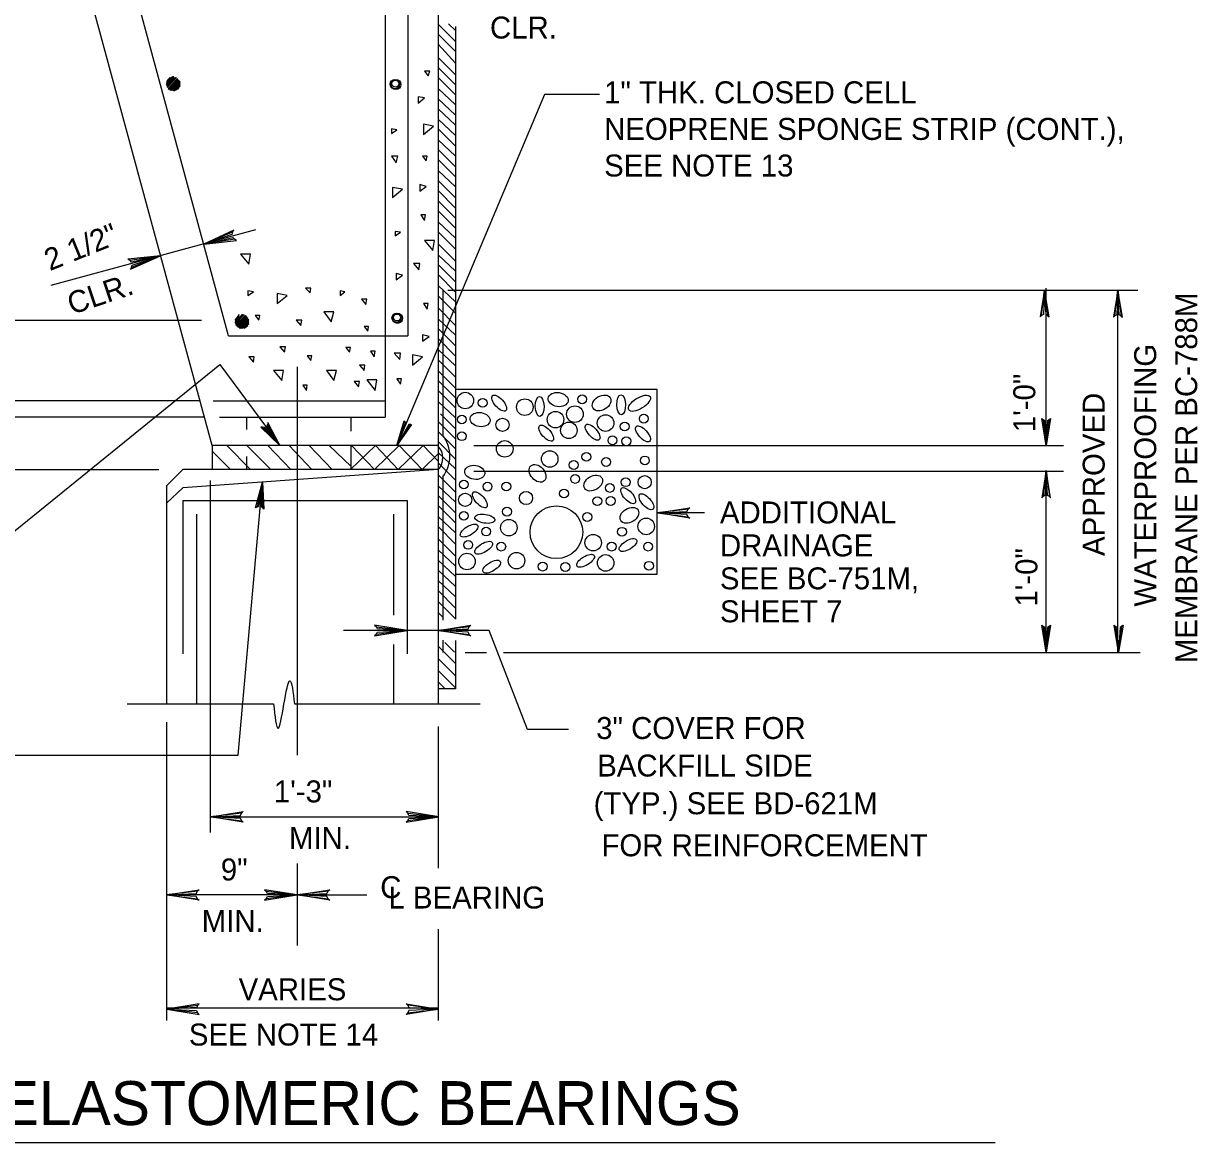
# Model space of a CAD drawing. Extents: x 640009 to 641706, y 298547 to 299735.
# Drawn here: x 640480.1 to 640640.5, y 298864.4 to 299017.2 of the extents above; entities that cross this region are included whole.
import ezdxf

# ---------------------------------------------------------------- set-up
doc = ezdxf.new("R2010")
doc.units = 0
doc.layers.add('1', color=7, linetype='Continuous')

msp = doc.modelspace()

# ---------------------------------------------------------------- linework, layer by layer
at = {"layer": '1'}
for p, q in [((640536.74, 299073.94), (640536.74, 298959.5)), ((640532.61, 299068.69), (640532.61, 299014.94)), ((640508.11, 298974.56), (640484.77, 299060.46)), ((640505.86, 298959.56), (640480.36, 299053.44)), ((640529.49, 299051.81), (640529.49, 298963.44)), ((640539.11, 299016.79), (640539.11, 298935.88)), ((640532.61, 299014.94), (640532.61, 298981.69)), ((640551.28, 299007.52), (640531.11, 298959.56)), ((640558.79, 299007.52), (640551.28, 299007.52)), ((640511.77, 298989), (640483.82, 298981.41)), ((640532.61, 298982.31), (640532.61, 298974.56)), ((640537.36, 298980.79), (640537.36, 298960.94)), ((640538.04, 298980.79), (640632.32, 298980.79)), ((640619.78, 298959.56), (640619.78, 298981.04)), ((640629.58, 298931.31), (640629.58, 298980.79)), ((640453.19, 298976.69), (640504.41, 298976.69)), ((640508.11, 298974.56), (640532.61, 298974.56)), ((640464.53, 298936.31), (640506.9, 298970.62)), ((640506.9, 298970.62), (640515.11, 298959.56)), ((640517.49, 298970.31), (640517.49, 298917.29)), ((640504.11, 298965.69), (640465.39, 298965.69)), ((640505.99, 298965.69), (640529.49, 298965.69)), ((640504.74, 298963.44), (640413.24, 298963.44)), ((640506.86, 298963.44), (640529.49, 298963.44)), ((640510.61, 298961.75), (640510.61, 298963.44)), ((640524.86, 298961.54), (640524.86, 298963.44)), ((640505.86, 298959.56), (640505.86, 298956.31)), ((640505.86, 298959.56), (640505.86, 298956.31)), ((640524.86, 298959.56), (640505.86, 298959.56)), ((640524.78, 298956.31), (640528.16, 298959.56)), ((640524.86, 298956.31), (640524.86, 298959.56)), ((640536.74, 298959.56), (640524.86, 298959.56)), ((640528.03, 298956.31), (640531.41, 298959.56)), ((640531.29, 298956.31), (640534.67, 298959.56)), ((640536.74, 298959.56), (640536.74, 298956.31)), ((640541.6, 298959.56), (640622.15, 298959.56)), ((640510.61, 298956.31), (640510.61, 298958.06)), ((640534.54, 298956.31), (640536.74, 298958.43)), ((640460.32, 298956.31), (640498.58, 298956.31)), ((640499.61, 298954.06), (640501.86, 298956.31)), ((640536.74, 298956.31), (640501.86, 298953.81)), ((640505.86, 298956.31), (640501.86, 298956.31)), ((640524.86, 298956.31), (640505.86, 298956.31)), ((640536.74, 298956.31), (640524.86, 298956.31)), ((640536.74, 298956.31), (640536.74, 298924.31)), ((640541.6, 298956.06), (640622.15, 298956.06)), ((640619.78, 298931.31), (640619.78, 298956.06)), ((640499.61, 298954.06), (640499.61, 298924.31)), ((640505.61, 298954.81), (640505.61, 298906.71)), ((640537.36, 298955.31), (640537.36, 298935.74)), ((640499.61, 298951.69), (640501.86, 298953.81)), ((640509.4, 298917.29), (640512.65, 298953.55)), ((640501.86, 298952.06), (640532.52, 298952.06)), ((640501.86, 298952.06), (640501.86, 298931.13)), ((640505.61, 298951.81), (640505.61, 298951.81)), ((640532.52, 298952.06), (640532.52, 298931.13)), ((640503.74, 298950.18), (640503.74, 298924.31)), ((640530.64, 298950.18), (640530.64, 298936.41)), ((640573.13, 298950.36), (640566.65, 298950.36)), ((640536.74, 298934.32), (640523.81, 298934.32)), ((640543.68, 298934.32), (640536.74, 298934.32)), ((640548.95, 298920.8), (640543.68, 298934.32)), ((640530.64, 298932.39), (640530.64, 298924.31)), ((640537.36, 298933.01), (640537.36, 298931.31)), ((640539.11, 298932.94), (640539.11, 298926.34)), ((640540.4, 298931.31), (640543.34, 298931.31)), ((640545.65, 298931.31), (640632.61, 298931.31)), ((640539.11, 298926.34), (640536.74, 298926.34)), ((640494.24, 298924.31), (640514.24, 298924.31)), ((640517.11, 298924.31), (640542.49, 298924.31)), ((640499.61, 298921.81), (640499.61, 298881.07)), ((640536.74, 298921.19), (640536.74, 298901.88)), ((640554.54, 298920.8), (640548.95, 298920.8)), ((640433.57, 298917.29), (640509.4, 298917.29)), ((640536.74, 298908.84), (640505.61, 298908.84)), ((640517.49, 298902.5), (640517.49, 298891.31)), ((640517.49, 298898.2), (640499.61, 298898.2)), ((640517.49, 298898.2), (640527, 298898.2)), ((640536.74, 298893.53), (640536.74, 298881.07)), ((640536.74, 298882.75), (640499.61, 298882.75)), ((640431.62, 298864.4), (640612.82, 298864.4))]:
    msp.add_line(p, q, dxfattribs=at)
for points in [[(640539.11, 299014.73), (640536.74, 299017.1)], [(640539.11, 299016.25), (640538.15, 299017.15)], [(640539.11, 299013.35), (640536.74, 299015.73)], [(640539.11, 299011.78), (640536.74, 299014.35)], [(640539.11, 299010.2), (640536.74, 299012.57)], [(640539.11, 299008.82), (640536.74, 299011.2)], [(640499.61, 299008.94), (640500.49, 299009.94)], [(640499.61, 299008.81), (640500.61, 299009.94)], [(640499.61, 299008.94), (640500.61, 299009.94)], [(640499.61, 299009.06), (640500.49, 299009.94)], [(640499.61, 299008.69), (640500.74, 299009.81)], [(640499.61, 299009.19), (640500.24, 299009.81)], [(640499.74, 299008.44), (640500.99, 299009.81)], [(640499.74, 299008.56), (640500.99, 299009.81)], [(640499.74, 299008.56), (640500.86, 299009.81)], [(640499.74, 299009.31), (640500.11, 299009.81)], [(640499.86, 299008.31), (640501.11, 299009.69)], [(640499.86, 299008.31), (640501.11, 299009.69)], [(640499.86, 299008.19), (640501.24, 299009.56)], [(640499.99, 299008.19), (640501.24, 299009.56)], [(640499.99, 299008.19), (640501.36, 299009.44)], [(640500.11, 299008.06), (640501.36, 299009.44)], [(640500.24, 299008.06), (640501.36, 299009.31)], [(640500.24, 299008.06), (640501.49, 299009.31)], [(640500.24, 299008.06), (640501.36, 299009.31)], [(640500.36, 299008.06), (640501.49, 299009.19)], [(640500.49, 299008.06), (640501.49, 299009.06)], [(640500.61, 299007.94), (640501.49, 299008.94)], [(640500.74, 299008.06), (640501.49, 299008.81)], [(640500.86, 299008.06), (640501.49, 299008.69)], [(640539.11, 299007.45), (640536.74, 299009.82)], [(640501.11, 299008.19), (640501.36, 299008.44)], [(640539.11, 299006.1), (640536.74, 299008.32)], [(640539.11, 299004.7), (640536.74, 299006.92)], [(640539.11, 299003.3), (640536.74, 299005.52)], [(640539.11, 299001.9), (640536.74, 299004.12)], [(640539.11, 299000.45), (640536.74, 299002.82)], [(640539.11, 298999.1), (640536.74, 299001.32)], [(640539.11, 298997.62), (640536.74, 299000)], [(640539.11, 298996.25), (640536.74, 298998.63)], [(640539.11, 298994.9), (640536.74, 298997.13)], [(640539.11, 298993.37), (640536.74, 298995.75)], [(640539.11, 298992), (640536.74, 298994.38)], [(640539.11, 298990.62), (640536.74, 298993)], [(640539.11, 298989.25), (640536.74, 298991.63)], [(640539.11, 298987.9), (640536.74, 298990.13)], [(640508.66, 298988.73), (640508.57, 298988.38), (640504.71, 298987.08), (640508.66, 298988.73), (640508.81, 298988.97), (640504.71, 298987.08), (640508.68, 298987.98), (640508.92, 298987.73), (640504.71, 298987.08), (640509.2, 298987.57), (640508.92, 298987.73)], [(640539.11, 298986.37), (640536.74, 298988.75)], [(640539.11, 298984.72), (640536.74, 298987.09)], [(640494.86, 298983.86), (640494.95, 298984.21), (640498.82, 298985.48), (640494.86, 298983.86), (640494.71, 298983.63), (640498.82, 298985.48), (640494.84, 298984.62), (640494.61, 298984.87), (640498.82, 298985.48), (640494.33, 298985.03), (640494.61, 298984.87)], [(640539.11, 298983.37), (640536.74, 298985.59)], [(640539.11, 298981.9), (640536.74, 298984.27)], [(640539.11, 298980.52), (640536.74, 298982.9)], [(640539.11, 298979.17), (640536.74, 298981.4)], [(640539.11, 298977.65), (640536.74, 298980.02)], [(640620.02, 298977.3), (640619.76, 298977.45), (640619.57, 298980.84), (640620.02, 298977.3), (640620.18, 298977.13), (640619.57, 298980.84), (640619.41, 298977.45), (640619.16, 298977.32), (640619.57, 298980.84), (640618.97, 298977.13), (640619.16, 298977.32)], [(640630.03, 298977.25), (640629.77, 298977.4), (640629.58, 298980.79), (640630.03, 298977.25), (640630.19, 298977.08), (640629.58, 298980.79), (640629.42, 298977.4), (640629.16, 298977.27), (640629.58, 298980.79), (640628.98, 298977.08), (640629.16, 298977.27)], [(640539.11, 298975.98), (640536.74, 298978.36)], [(640508.99, 298976.19), (640510.24, 298977.44)], [(640508.99, 298976.31), (640510.11, 298977.44)], [(640508.99, 298976.31), (640509.99, 298977.44)], [(640508.99, 298976.44), (640509.99, 298977.44)], [(640508.99, 298976.69), (640509.61, 298977.44)], [(640508.99, 298976.56), (640509.61, 298977.19)], [(640509.11, 298975.94), (640510.49, 298977.31)], [(640509.11, 298976.06), (640510.36, 298977.31)], [(640509.11, 298976.06), (640510.36, 298977.31)], [(640509.24, 298975.81), (640510.61, 298977.19)], [(640509.24, 298975.94), (640510.49, 298977.19)], [(640509.36, 298975.69), (640510.74, 298977.06)], [(640509.36, 298975.81), (640510.61, 298977.06)], [(640509.49, 298975.69), (640510.74, 298976.94)], [(640509.49, 298975.69), (640510.74, 298976.94)], [(640509.49, 298975.69), (640510.74, 298976.81)], [(640509.61, 298975.56), (640510.86, 298976.81)], [(640509.74, 298975.56), (640510.86, 298976.69)], [(640509.86, 298975.56), (640510.86, 298976.56)], [(640509.86, 298975.56), (640510.86, 298976.44)], [(640539.11, 298974.63), (640536.74, 298976.86)], [(640509.99, 298975.56), (640510.86, 298976.31)], [(640510.24, 298975.56), (640510.86, 298976.19)], [(640510.36, 298975.69), (640510.74, 298975.94)], [(640539.11, 298973.16), (640536.74, 298975.53)], [(640539.11, 298971.78), (640536.74, 298974.16)], [(640539.11, 298970.43), (640536.74, 298972.66)], [(640539.11, 298968.91), (640536.74, 298971.28)], [(640539.11, 298967.42), (640536.74, 298969.79)], [(640539.11, 298966.1), (640536.74, 298968.47)], [(640539.11, 298964.72), (640536.74, 298967.1)], [(640539.11, 298963.37), (640536.74, 298965.6)], [(640539.11, 298961.85), (640537.06, 298963.9)], [(640512.74, 298962.06), (640512.99, 298962.06), (640515.11, 298959.56), (640512.74, 298962.06), (640512.49, 298962.06), (640515.11, 298959.56), (640513.36, 298962.31), (640513.49, 298962.44), (640515.11, 298959.56), (640513.49, 298962.69), (640513.49, 298962.44)], [(640532.99, 298962.44), (640532.74, 298962.44), (640531.11, 298959.56), (640532.99, 298962.44), (640533.11, 298962.44), (640531.11, 298959.56), (640532.36, 298962.56), (640532.24, 298962.69), (640531.11, 298959.56), (640532.11, 298962.94), (640532.24, 298962.69)], [(640539.11, 298960.47), (640536.74, 298962.85)], [(640620.23, 298963.1), (640619.97, 298962.95), (640619.78, 298959.56), (640620.23, 298963.1), (640620.39, 298963.28), (640619.78, 298959.56), (640619.62, 298962.95), (640619.37, 298963.09), (640619.78, 298959.56), (640619.18, 298963.28), (640619.37, 298963.09)], [(640539.11, 298959.1), (640536.74, 298961.47)], [(640508.36, 298956.31), (640505.86, 298958.81)], [(640511.11, 298956.31), (640507.86, 298959.56)], [(640513.86, 298956.31), (640510.61, 298959.56)], [(640516.61, 298956.31), (640513.49, 298959.56)], [(640519.49, 298956.31), (640516.36, 298959.56)], [(640522.24, 298956.31), (640519.11, 298959.56)], [(640524.86, 298956.69), (640521.86, 298959.56)], [(640528.03, 298956.31), (640524.91, 298959.56)], [(640531.29, 298956.31), (640528.16, 298959.56)], [(640534.54, 298956.31), (640531.41, 298959.56)], [(640536.74, 298957.41), (640534.67, 298959.56)], [(640539.11, 298957.72), (640536.74, 298960.1)], [(640539.11, 298956.37), (640536.74, 298958.6)], [(640539.11, 298954.85), (640536.74, 298957.22)], [(640539.11, 298953.19), (640536.74, 298955.57)], [(640620.22, 298952.61), (640619.96, 298952.76), (640619.77, 298956.15), (640620.22, 298952.61), (640620.37, 298952.44), (640619.77, 298956.15), (640619.61, 298952.76), (640619.35, 298952.63), (640619.77, 298956.15), (640619.17, 298952.44), (640619.35, 298952.63)], [(640512.01, 298951.19), (640512.22, 298951.32), (640512.74, 298954.56), (640512.01, 298951.19), (640511.8, 298951.06), (640512.74, 298954.56), (640512.57, 298951.24), (640512.8, 298951.09), (640512.74, 298954.56), (640512.93, 298950.88), (640512.8, 298951.09)], [(640539.11, 298951.84), (640536.74, 298954.07)], [(640539.11, 298950.37), (640536.74, 298952.74)], [(640539.11, 298948.99), (640536.74, 298951.37)], [(640570.89, 298949.82), (640570.72, 298950.14), (640566.65, 298950.36), (640570.89, 298949.82), (640571.1, 298949.63), (640566.65, 298950.36), (640570.72, 298950.56), (640570.87, 298950.86), (640566.65, 298950.36), (640571.1, 298951.08), (640570.87, 298950.86)], [(640539.11, 298947.64), (640536.74, 298949.87)], [(640539.11, 298946.12), (640536.74, 298948.49)], [(640539.11, 298944.45), (640536.74, 298946.83)], [(640539.11, 298943.1), (640536.74, 298945.33)], [(640539.11, 298941.7), (640536.74, 298943.93)], [(640539.11, 298940.3), (640536.74, 298942.53)], [(640539.08, 298938.93), (640536.74, 298941.13)], [(640539.11, 298937.38), (640536.74, 298939.75)], [(640539.11, 298935.91), (640536.74, 298938.28)], [(640537.43, 298936.08), (640536.74, 298936.78)], [(640528.28, 298933.78), (640528.45, 298934.1), (640532.52, 298934.32), (640528.28, 298933.78), (640528.06, 298933.6), (640532.52, 298934.32), (640528.45, 298934.52), (640528.29, 298934.82), (640532.52, 298934.32), (640528.06, 298935.04), (640528.29, 298934.82)], [(640540.98, 298933.78), (640540.81, 298934.1), (640536.74, 298934.32), (640540.98, 298933.78), (640541.19, 298933.6), (640536.74, 298934.32), (640540.81, 298934.52), (640540.96, 298934.82), (640536.74, 298934.32), (640541.19, 298935.04), (640540.96, 298934.82)], [(640620.22, 298934.89), (640619.96, 298934.74), (640619.77, 298931.35), (640620.22, 298934.89), (640620.37, 298935.06), (640619.77, 298931.35), (640619.61, 298934.74), (640619.35, 298934.87), (640619.77, 298931.35), (640619.17, 298935.06), (640619.35, 298934.87)], [(640630.13, 298934.89), (640629.87, 298934.74), (640629.68, 298931.35), (640630.13, 298934.89), (640630.29, 298935.06), (640629.68, 298931.35), (640629.52, 298934.74), (640629.27, 298934.87), (640629.68, 298931.35), (640629.08, 298935.06), (640629.27, 298934.87)], [(640539.11, 298929.81), (640536.74, 298932.18)], [(640538.97, 298931.35), (640537.63, 298932.69)], [(640539.11, 298928.11), (640536.74, 298930.49)], [(640539.11, 298926.48), (640536.74, 298928.86)], [(640537.7, 298926.34), (640536.74, 298927.31)], [(640509.9, 298908.32), (640509.73, 298908.63), (640505.65, 298908.86), (640509.9, 298908.32), (640510.11, 298908.13), (640505.65, 298908.86), (640509.73, 298909.05), (640509.88, 298909.36), (640505.65, 298908.86), (640510.11, 298909.58), (640509.88, 298909.36)], [(640532.57, 298908.32), (640532.75, 298908.63), (640536.82, 298908.86), (640532.57, 298908.32), (640532.36, 298908.13), (640536.82, 298908.86), (640532.75, 298909.05), (640532.59, 298909.36), (640536.82, 298908.86), (640532.36, 298909.58), (640532.59, 298909.36)], [(640503.86, 298897.66), (640503.68, 298897.98), (640499.61, 298898.2), (640503.86, 298897.66), (640504.07, 298897.48), (640499.61, 298898.2), (640503.68, 298898.4), (640503.84, 298898.7), (640499.61, 298898.2), (640504.07, 298898.92), (640503.84, 298898.7)], [(640513.24, 298897.66), (640513.42, 298897.98), (640517.49, 298898.2), (640513.24, 298897.66), (640513.03, 298897.48), (640517.49, 298898.2), (640513.42, 298898.4), (640513.26, 298898.7), (640517.49, 298898.2), (640513.03, 298898.92), (640513.26, 298898.7)], [(640521.73, 298897.66), (640521.55, 298897.98), (640517.49, 298898.2), (640521.73, 298897.66), (640521.94, 298897.48), (640517.49, 298898.2), (640521.55, 298898.4), (640521.71, 298898.7), (640517.49, 298898.2), (640521.94, 298898.92), (640521.71, 298898.7)], [(640503.9, 298883.15), (640503.73, 298882.83), (640499.66, 298882.61), (640503.9, 298883.15), (640504.11, 298883.33), (640499.66, 298882.61), (640503.73, 298882.41), (640503.88, 298882.11), (640499.66, 298882.61), (640504.11, 298881.88), (640503.88, 298882.11)], [(640532.57, 298883.15), (640532.75, 298882.83), (640536.82, 298882.61), (640532.57, 298883.15), (640532.36, 298883.33), (640536.82, 298882.61), (640532.75, 298882.41), (640532.59, 298882.11), (640536.82, 298882.61), (640532.36, 298881.88), (640532.59, 298882.11)]]:
    msp.add_lwpolyline(points, dxfattribs=at)
for points in [[(640534.86, 299010.69), (640535.36, 299010.06), (640535.61, 299010.69)], [(640533.99, 299006.31), (640534.86, 299007.06), (640533.99, 299007.19)], [(640530.36, 299002.19), (640531.11, 299002.69), (640530.36, 299002.81)], [(640534.74, 299002.06), (640536.11, 299003.19), (640534.74, 299003.44)], [(640530.36, 298999.06), (640530.99, 298998.19), (640531.24, 298999.06)], [(640534.61, 298999.06), (640535.11, 298998.44), (640535.24, 298999.06)], [(640530.49, 298993.44), (640531.86, 298994.56), (640530.49, 298994.81)], [(640534.24, 298994.31), (640535.11, 298994.94), (640534.24, 298995.19)], [(640534.36, 298991.06), (640534.86, 298990.31), (640534.99, 298991.06)], [(640530.86, 298988.19), (640531.61, 298988.69), (640530.86, 298988.81)], [(640534.86, 298987.56), (640535.99, 298986.19), (640536.24, 298987.56)], [(640509.74, 298985.69), (640510.86, 298984.31), (640511.11, 298985.69)], [(640533.36, 298984.44), (640534.11, 298983.56), (640534.24, 298984.44)], [(640530.99, 298982.19), (640531.86, 298982.81), (640530.99, 298983.06)], [(640510.74, 298980.06), (640511.49, 298980.56), (640510.74, 298980.69)], [(640514.74, 298978.94), (640516.11, 298980.06), (640514.74, 298980.31)], [(640518.61, 298981.06), (640519.24, 298980.44), (640519.36, 298981.06)], [(640523.36, 298980.06), (640523.99, 298980.56), (640523.36, 298980.69)], [(640526.24, 298979.56), (640526.86, 298978.81), (640526.99, 298979.56)], [(640534.74, 298978.94), (640535.24, 298978.19), (640535.36, 298978.94)], [(640511.74, 298977.31), (640512.24, 298976.69), (640512.36, 298977.31)], [(640517.36, 298976.69), (640517.99, 298975.94), (640518.11, 298976.69)], [(640521.11, 298977.81), (640522.11, 298976.44), (640522.49, 298977.81)], [(640526.61, 298975.81), (640527.11, 298975.19), (640527.24, 298975.81)], [(640534.61, 298973.81), (640535.49, 298974.44), (640534.61, 298974.69)], [(640510.86, 298971.69), (640511.49, 298970.94), (640511.61, 298971.69)], [(640515.11, 298973.06), (640515.74, 298972.31), (640515.86, 298973.06)], [(640518.86, 298971.81), (640519.36, 298971.19), (640519.49, 298971.81)], [(640524.11, 298972.94), (640524.61, 298972.31), (640524.74, 298972.94)], [(640527.49, 298972.44), (640527.99, 298971.69), (640528.11, 298972.44)], [(640530.74, 298972.19), (640531.49, 298971.31), (640531.61, 298972.19)], [(640533.24, 298970.56), (640534.61, 298971.69), (640533.24, 298971.94)], [(640525.99, 298970.56), (640526.61, 298969.81), (640526.74, 298970.56)], [(640514.24, 298969.81), (640515.36, 298968.44), (640515.61, 298969.81)], [(640521.49, 298969.81), (640522.49, 298968.44), (640522.86, 298969.81)], [(640526.99, 298968.56), (640528.11, 298967.06), (640528.36, 298968.56)], [(640531.11, 298968.69), (640531.61, 298967.94), (640531.74, 298968.69)], [(640518.24, 298967.81), (640518.74, 298967.06), (640518.86, 298967.81)], [(640525.24, 298968.31), (640525.86, 298967.56), (640525.99, 298968.31)], [(640566.65, 298967.22), (640539.11, 298967.22), (640539.11, 298942.02), (640566.65, 298942.02)]]:
    msp.add_lwpolyline(points, close=True, dxfattribs=at)
for centre, radius in [((640530.82, 299008.92), 0.636), ((640530.94, 299008.86), 0.693), ((640530.88, 299008.98), 0.474), ((640531.06, 298977), 0.636), ((640531.17, 298976.94), 0.693), ((640531.11, 298977.05), 0.474), ((640540.44, 298965.71), 1.13), ((640542.82, 298965.4), 0.605), ((640548.57, 298964.81), 1.13), ((640556.4, 298965.88), 0.605), ((640539.97, 298963.12), 0.605), ((640552.76, 298963.1), 1.13), ((640555.41, 298963.85), 1.13), ((640559.6, 298962.63), 1.13), ((640564.82, 298963.24), 0.605), ((640545.51, 298962.4), 0.9), ((640554.59, 298961.64), 1.13), ((640562.21, 298962.17), 0.605), ((640539.97, 298960.84), 0.605), ((640560.54, 298960.27), 0.605), ((640562.44, 298960.15), 0.605), ((640545.83, 298959.11), 1.13), ((640551.97, 298957.73), 1.13), ((640555.25, 298956.91), 0.605), ((640556.98, 298958.02), 0.605), ((640559.67, 298957.32), 0.605), ((640564.97, 298957.53), 0.605), ((640555.44, 298955.01), 0.605), ((640540.24, 298954.25), 0.605), ((640543.48, 298953.96), 0.605), ((640546.05, 298953.97), 0.605), ((640560.18, 298953.78), 0.605), ((640562.35, 298954.56), 0.605), ((640564.94, 298954.56), 0.9), ((640540.41, 298952.15), 0.9), ((640548.74, 298952.4), 0.9), ((640553.92, 298953.02), 0.605), ((640558.47, 298951.97), 0.605), ((640560.29, 298952), 0.605), ((640546.13, 298950.54), 0.605), ((640552.88, 298947.73), 3.6), ((640540.24, 298949.97), 0.605), ((640546.39, 298948.35), 1.13), ((640557.1, 298949.81), 0.605), ((640565.15, 298948.52), 1.13), ((640543.29, 298947.82), 0.605), ((640561.85, 298947.79), 0.605), ((640540.84, 298946), 0.605), ((640545.35, 298945.77), 0.605), ((640557.91, 298946.3), 1.13), ((640560.43, 298945.77), 0.605), ((640565.41, 298945.77), 0.605), ((640540.67, 298943.73), 1.13), ((640547.44, 298943.85), 1.13), ((640559.61, 298943.54), 1.13), ((640551, 298943.04), 0.605), ((640554.11, 298942.98), 0.605), ((640565.53, 298943.15), 0.605)]:
    msp.add_circle(centre, radius, dxfattribs=at)
msp.add_arc((640533.88, 298958.12), 4.47, 321.0382, 38.9618, dxfattribs=at)
for centre, major_axis, ratio in [((640553.13, 298965.84), (1.36, -0.2), 0.696126), ((640545.07, 298965.36), (0.91, -1.02), 0.438009), ((640550.6, 298964.91), (0.04, -1.37), 0.438009), ((640559.06, 298965.38), (1.17, 0.72), 0.696126), ((640561.73, 298965.14), (0.04, -1.37), 0.438009), ((640564.22, 298965.34), (1.46, 0.9), 0.438009), ((640542.46, 298963.11), (1.36, -0.2), 0.696126), ((640551.49, 298961.26), (0.91, -1.02), 0.438009), ((640557.83, 298961.39), (0.91, -1.02), 0.438009), ((640564.71, 298961.16), (0.91, -1.02), 0.438009), ((640541.73, 298955.9), (1.36, -0.2), 0.696126), ((640550.31, 298955.77), (0.91, -1.02), 0.696126), ((640557.92, 298954.44), (1.17, 0.72), 0.696126), ((640562.69, 298952.72), (0.91, -1.02), 0.438009), ((640542.43, 298952.16), (0.91, -1.02), 0.438009), ((640565.18, 298951.89), (0.91, -1.02), 0.438009), ((640562.86, 298950.04), (1.17, 0.72), 0.696126), ((640543.11, 298949.57), (1.36, -0.2), 0.438009), ((640540.97, 298947.95), (1.17, 0.72), 0.438009), ((640542.95, 298945.61), (1.17, 0.72), 0.438009), ((640562.67, 298945.98), (1.17, 0.72), 0.438009), ((640556.87, 298943.83), (1.17, 0.72), 0.438009), ((640544.04, 298943.03), (1.17, 0.72), 0.438009)]:
    msp.add_ellipse(centre, major_axis=major_axis, ratio=ratio, dxfattribs=at)
msp.add_ellipse((640534.57, 298957.89), major_axis=(2.81, 0), ratio=0.9, start_param=5.608799, end_param=6.973497, dxfattribs=at)
msp.add_spline([(640514.24, 298924.31), (640514.86, 298920.94), (640516.49, 298927.44), (640517.11, 298924.31)], degree=3, dxfattribs=at)

# ---------------------------------------------------------------- texts
for s, height, p in [('CLR.', 3, (640543.81, 299015.14)), ('1" THK. CLOSED CELL', 3, (640559.4, 299006.3)), ('NEOPRENE SPONGE STRIP (CONT.),', 3, (640559.4, 299001.3)), ('SEE NOTE 13', 3, (640559.4, 298996.3)), ('ADDITIONAL', 3, (640575.22, 298948.93)), ('DRAINAGE', 3, (640575.22, 298944.43)), ('SEE BC-751M,', 3, (640575.22, 298939.93)), ('SHEET 7', 3, (640575.22, 298935.43)), ('3" COVER FOR', 3, (640558.32, 298919.49)), ('BACKFILL SIDE', 3, (640558.46, 298914.37)), ('1\'-3"', 3, (640514.29, 298910.84)), ('(TYP.) SEE BD-621M', 3, (640557.97, 298909.22)), ('MIN.', 3, (640516.36, 298904.47)), ('FOR REINFORCEMENT', 3, (640559.04, 298903.48)), ('9"', 3, (640507.05, 298900.18)), ('C', 3, (640528.82, 298897.76)), ('L BEARING', 3, (640529.94, 298896.35)), ('MIN.', 3, (640504.44, 298893.16)), ('VARIES', 3, (640509.48, 298883.82)), ('SEE NOTE 14', 3, (640502.68, 298877.64)), ('SECTION - ELASTOMERIC BEARINGS', 6, (640434.06, 298866.78))]:
    msp.add_text(s, height=height, dxfattribs=at).set_placement(p)
for s, rotation, p in [('2 1/2"', 21.9839, (640483.69, 298983.37)), ('CLR.', 18.5764, (640486.7, 298977.4)), ('MEMBRANE PER BC-788M', 90, (640640.41, 298929.85)), ('WATERPROOFING', 90, (640634.81, 298937.57)), ('1\'-0"', 90, (640618.29, 298961.39)), ('APPROVED', 90, (640627.77, 298944.48)), ('1\'-0"', 90, (640618.58, 298937.57))]:
    msp.add_text(s, height=3, rotation=rotation, dxfattribs=at).set_placement(p)

doc.saveas('drawing.dxf')
